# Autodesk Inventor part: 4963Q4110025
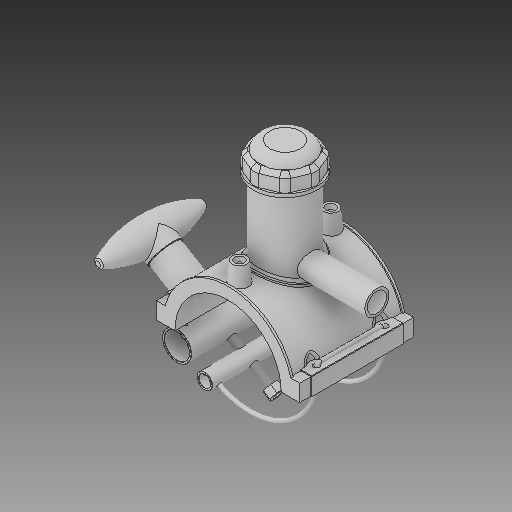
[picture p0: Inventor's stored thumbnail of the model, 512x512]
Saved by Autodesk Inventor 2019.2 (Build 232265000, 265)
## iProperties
Created: 2017-07
Part Number: 4963Q4110025
Material: Generic
Description: PLASSON TAPPING SADDLE 110x25
Document SubType Name: Modeling
Designer: KIM
Mass: 1712.7 g
Surface Area: 2671.49 cm^2
Volume: 1712.7 cm^3
Density: 1 g/cm^3
Appearance: Default
Author: KIM
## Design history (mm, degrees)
derived "4963Q4 (new clamping).ipt"
feature "Solid1::4963Q4 (new clamping).ipt"
feature "Solid2::4963Q4 (new clamping).ipt"
feature "Solid4::4963Q4 (new clamping).ipt"
feature "Solid5::4963Q4 (new clamping).ipt"
feature "Solid6::4963Q4 (new clamping).ipt"
feature "Solid7::4963Q4 (new clamping).ipt"
feature "Solid8::4963Q4 (new clamping).ipt"
feature "Solid9::4963Q4 (new clamping).ipt" dims "d70" = 15
feature "Solid10::4963Q4 (new clamping).ipt"
tag "TaggingFeature1"
body "Solid1"
body "Solid2"
body "Solid3"
body "Solid4"
body "Solid5"
body "Solid6"
body "Solid7"
other parameters: "d2" = 148, "d4" = 118, "d5" = 0, "d6" = 0.1, "d8" = 0, "d19" = 6, "d20" = 6, "d21" = 70.8, "d23" = 0, "d24" = 35.4, "d40" = 68.64, "d41" = 66, "d43" = 0, "d45" = 0, "d47" = 136.8, "d72" = 0, "d73" = 6, "d77" = 5.5, "d78" = 85, "d79" = 15, "d80" = 47.2, "d82" = 5 deg, "d84" = 4, "d85" = 14, "d86" = 0, "d87" = 3, "d88" = 0, "d89" = 1, "d90" = 1, "d91" = 94.4, "d92" = 0, "d93" = 0.5, "d94" = 57.89474, "d96" = 134.64, "d97" = 2.36, "d98" = 0, "d102" = 1.1, "d120" = 140 deg, "d121" = 24.228, "d122" = 20 deg, "d123" = 264, "d124" = 79.2, "d126" = 0, "d143" = 113.3, "d145" = 16.92308, "d149" = 1.65, "d150" = 18.61538, "d153" = 118, "d154" = 0, "d156" = 66, "d157" = 160 deg, "d159" = 4.4, "d161" = 1.65, "d162" = 70.8, "d163" = 0, "d164" = 55, "d167" = 11, "d168" = 64.39024, "d170" = 3.75, "d172" = 0, "d173" = 1, "d175" = 55, "d176" = 20 deg, "d177" = 7.7, "d178" = 22, "d180" = 0, "d183" = 8.8, "d184" = 6.16, "d185" = 38.35, "d186" = 38.35, "d187" = 66, "d188" = 6.6, "d189" = 7.7, "d190" = 0, "d191" = 99, "d193" = 7, "d194" = 4.13, "d195" = 90 deg, "d197" = 0, "d199" = 0, "d200" = 11, "d203" = 114, "d204" = 62.7, "d205" = 46.2, "d206" = 56.1, "d207" = 85.5, "d208" = 88.92, "d209" = 106.02, "d210" = 56.76, "d211" = 66, "d212" = 52.8, "d213" = 3.15, "d216" = 0, "d217" = 11, "d218" = 11, "d219" = 2.2, "d224" = 0, "d230" = 4.4, "d245" = 35.4, "d246" = 35.4, "d247" = 6, "d248" = 6, "d257" = 71, "d258" = 95, "d260" = 25, "d263" = 148, "d265" = 0, "d267" = 13.00006, "d268" = 2.60001, "d269" = 2.60001, "d271" = 2.60001, "d273" = 0, "d274" = 23.56194, "d275" = 88, "d277" = 44, "d278" = 176, "d280" = 0, "d283" = 0, "d285" = 0, "d286" = 17.5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
